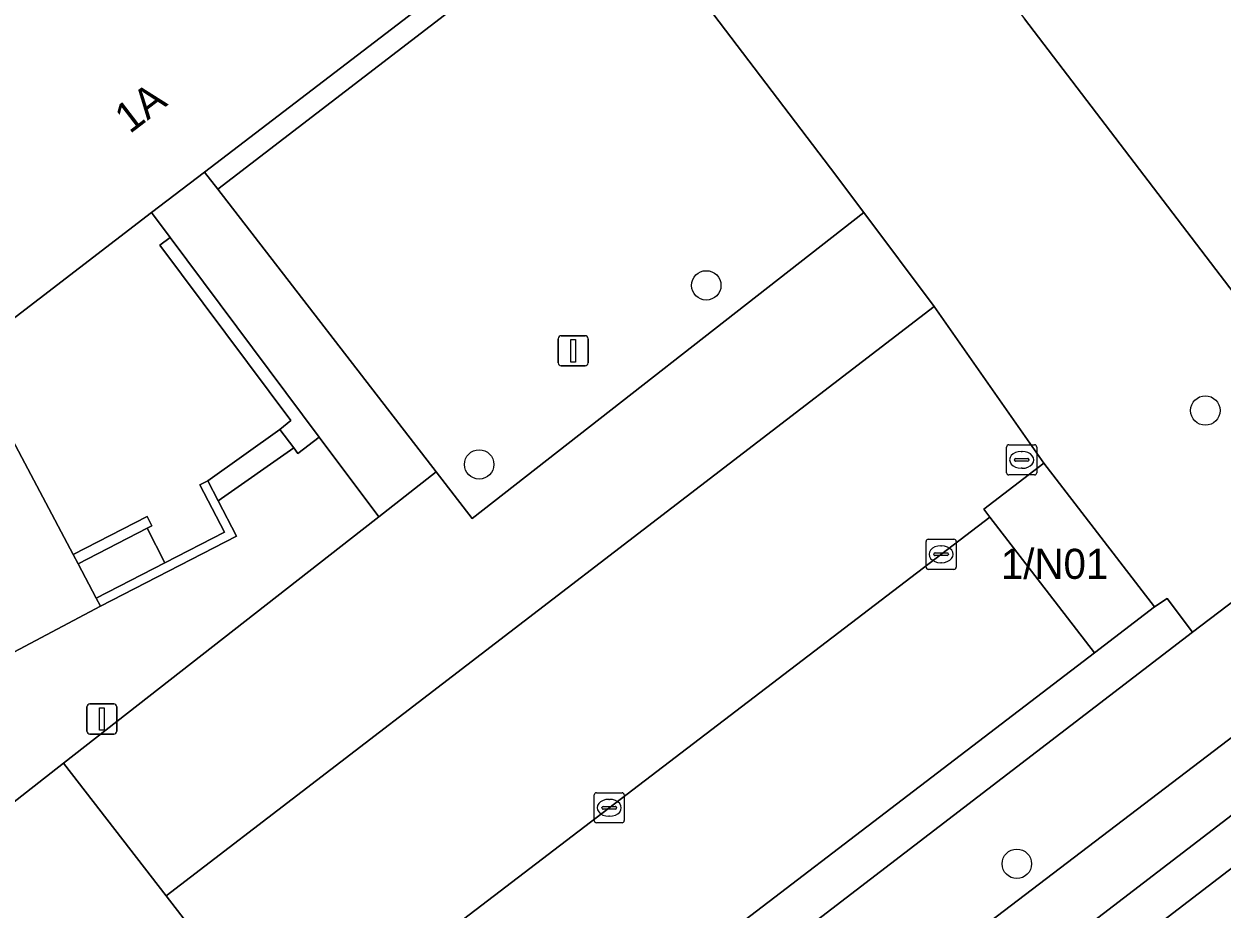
# Model space of a CAD drawing. Extents: x 159352 to 160617, y 385888 to 387323.
# Drawn here: x 159906.78 to 159946.57, y 386522.75 to 386552.16 of the extents above; entities that cross this region are included whole.
import ezdxf

# ---------------------------------------------------------------- set-up
doc = ezdxf.new("R2010")
doc.units = 0
for name, color, linetype in [('IMGEO_Boom', 7, 'Continuous'), ('IMGEO_Erf', 7, 'Continuous'), ('IMGEO_Groenvoorziening', 7, 'Continuous'), ('IMGEO_Haag', 7, 'Continuous'), ('IMGEO_Kolk', 7, 'Continuous'), ('IMGEO_Lichtmast', 7, 'Continuous'), ('IMGEO_Muur', 7, 'Continuous'), ('IMGEO_Pand', 7, 'Continuous'), ('IMGEO_Pand_nummerreeks', 7, 'Continuous'), ('IMGEO_Parkeervlak_gesloten', 7, 'Continuous'), ('IMGEO_Parkeervlak_open', 7, 'Continuous'), ('IMGEO_Rijbaan_lokaal_gesloten', 7, 'Continuous'), ('IMGEO_Rijbaan_lokaal_open', 7, 'Continuous'), ('IMGEO_Rioolput', 7, 'Continuous'), ('IMGEO_Voetpad_open', 7, 'Continuous')]:
    doc.layers.add(name, color=color, linetype=linetype)

msp = doc.modelspace()

# ---------------------------------------------------------------- linework, layer by layer
at = {"layer": 'IMGEO_Boom'}
for centre in [(159929.438, 386543.471), (159946.013, 386539.313), (159921.896, 386537.523), (159939.754, 386524.256)]:
    msp.add_circle(centre, 0.489, dxfattribs=at)
at = {"layer": 'IMGEO_Erf'}
msp.add_lwpolyline([(159918.853, 386623.383), (159898.089, 386607.292), (159922.277, 386575.578), (159940.008, 386552.331), (159951.895, 386536.745), (159972.553, 386552.445)], dxfattribs=at)
msp.add_lwpolyline([(159912.775, 386547.236), (159913.211, 386546.671), (159924.505, 386555.352), (159918.33, 386563.284), (159917.807, 386562.877), (159920.456, 386559.419), (159923.497, 386555.45)], close=True, dxfattribs=at)
at = {"layer": 'IMGEO_Groenvoorziening'}
for points in [[(159920.36, 386564.743), (159918.33, 386563.284), (159924.505, 386555.352), (159913.211, 386546.671), (159920.47, 386537.273), (159921.661, 386535.731), (159934.672, 386545.892), (159933.568, 386547.368)], [(159942.332, 386531.263), (159923.967, 386517.223), (159924.868, 386516.046), (159945.59, 386531.953), (159944.745, 386533.066), (159944.324, 386532.797)]]:
    msp.add_lwpolyline(points, close=True, dxfattribs=at)
msp.add_lwpolyline([(159920.36, 386564.743), (159933.568, 386547.368), (159934.672, 386545.892), (159937.004, 386542.774), (159940.649, 386537.568), (159944.324, 386532.797), (159944.745, 386533.066), (159945.59, 386531.953), (159951.895, 386536.745), (159940.008, 386552.331)], dxfattribs=at)
at = {"layer": 'IMGEO_Haag'}
msp.add_lwpolyline([(159942.332, 386531.263), (159923.967, 386517.223), (159924.868, 386516.046), (159945.59, 386531.953), (159944.745, 386533.066), (159944.324, 386532.797)], close=True, dxfattribs=at)
at = {"layer": 'IMGEO_Kolk'}
for p, q in [((159936.813, 386535.038), (159937.665, 386535.038)), ((159936.738, 386534.112), (159936.738, 386534.964)), ((159937.226, 386534.818), (159937.251, 386534.818)), ((159937.739, 386534.964), (159937.739, 386534.112)), ((159936.997, 386534.532), (159936.997, 386534.544)), ((159937.435, 386534.495), (159937.037, 386534.495)), ((159937.04, 386534.581), (159937.438, 386534.581)), ((159937.249, 386534.258), (159937.224, 386534.258)), ((159937.481, 386534.544), (159937.481, 386534.532)), ((159937.665, 386534.038), (159936.813, 386534.038)), ((159925.714, 386525.691), (159925.714, 386526.543)), ((159925.789, 386526.617), (159926.641, 386526.617)), ((159926.202, 386526.397), (159926.227, 386526.397)), ((159926.715, 386526.543), (159926.715, 386525.691)), ((159925.973, 386526.111), (159925.973, 386526.123)), ((159926.411, 386526.074), (159926.013, 386526.074)), ((159926.016, 386526.16), (159926.414, 386526.16)), ((159926.225, 386525.837), (159926.2, 386525.837)), ((159926.457, 386526.123), (159926.457, 386526.111)), ((159926.641, 386525.617), (159925.789, 386525.617))]:
    msp.add_line(p, q, dxfattribs=at)
for points in [[(159936.813, 386535.038), (159937.665, 386535.038)], [(159936.738, 386534.112), (159936.738, 386534.964)], [(159937.739, 386534.964), (159937.739, 386534.112)], [(159937.665, 386534.038), (159936.813, 386534.038)], [(159925.714, 386525.691), (159925.714, 386526.543)], [(159925.789, 386526.617), (159926.641, 386526.617)], [(159926.715, 386526.543), (159926.715, 386525.691)], [(159926.641, 386525.617), (159925.789, 386525.617)]]:
    msp.add_lwpolyline(points, dxfattribs=at)
for centre, radius, start, end in [((159936.815, 386534.962), 0.0765, 91.552, 178.448), ((159936.815, 386534.962), 0.0765, 91.552, 178.448), ((159937.663, 386534.962), 0.0765, 1.552, 88.448), ((159937.663, 386534.962), 0.0765, 1.552, 88.448), ((159937.037, 386534.541), 0.0403, 85.8775, 175.7526), ((159937.034, 386534.531), 0.0366, 178.938, 274.7102), ((159937.438, 386534.538), 0.043, 264.8664, 352.4533), ((159937.442, 386534.543), 0.0386, 1.7309, 96.639), ((159936.815, 386534.114), 0.0765, 181.552, 268.448), ((159936.815, 386534.114), 0.0765, 181.552, 268.448), ((159937.663, 386534.114), 0.0765, 271.552, 358.448), ((159937.663, 386534.114), 0.0765, 271.552, 358.448), ((159925.791, 386526.541), 0.0765, 91.552, 178.448), ((159925.791, 386526.541), 0.0765, 91.552, 178.448), ((159926.639, 386526.541), 0.0765, 1.552, 88.448), ((159926.639, 386526.541), 0.0765, 1.552, 88.448), ((159926.013, 386526.12), 0.0403, 85.8775, 175.7526), ((159926.01, 386526.11), 0.0366, 178.938, 274.7102), ((159926.414, 386526.117), 0.043, 264.8664, 352.4533), ((159926.418, 386526.122), 0.0386, 1.7309, 96.639), ((159925.791, 386525.693), 0.0765, 181.552, 268.448), ((159925.791, 386525.693), 0.0765, 181.552, 268.448), ((159926.639, 386525.693), 0.0765, 271.552, 358.448), ((159926.639, 386525.693), 0.0765, 271.552, 358.448)]:
    msp.add_arc(centre, radius, start, end, dxfattribs=at)
for centre, major_axis, ratio, start_param, end_param in [((159937.225, 386534.538), (-0.387, 0.002), 0.722429, 4.712389, 7.853982), ((159937.25, 386534.538), (-0.39, 0.002), 0.717154, 1.570796, 4.712389), ((159926.201, 386526.117), (-0.387, 0.002), 0.722429, 4.712389, 7.853982), ((159926.226, 386526.117), (-0.39, 0.002), 0.717154, 1.570796, 4.712389)]:
    msp.add_ellipse(centre, major_axis=major_axis, ratio=ratio, start_param=start_param, end_param=end_param, dxfattribs=at)
at = {"layer": 'IMGEO_Lichtmast'}
for p, q in [((159924.624, 386541.798), (159925.414, 386541.798)), ((159925.414, 386541.798), (159924.624, 386541.798)), ((159924.524, 386540.898), (159924.524, 386541.698)), ((159924.524, 386541.698), (159924.524, 386540.898)), ((159925.514, 386541.698), (159925.514, 386540.898)), ((159925.514, 386540.898), (159925.514, 386541.698)), ((159925.414, 386540.798), (159924.624, 386540.798)), ((159924.624, 386540.798), (159925.414, 386540.798)), ((159908.87, 386528.665), (159908.87, 386529.465)), ((159908.87, 386529.465), (159908.87, 386528.665)), ((159908.97, 386529.565), (159909.76, 386529.565)), ((159909.76, 386529.565), (159908.97, 386529.565)), ((159909.86, 386529.465), (159909.86, 386528.665)), ((159909.86, 386528.665), (159909.86, 386529.465)), ((159909.76, 386528.565), (159908.97, 386528.565)), ((159908.97, 386528.565), (159909.76, 386528.565))]:
    msp.add_line(p, q, dxfattribs=at)
for points in [[(159924.944, 386541.673), (159925.094, 386541.673), (159925.094, 386540.923), (159924.944, 386540.923), (159924.944, 386541.673)], [(159909.29, 386529.44), (159909.44, 386529.44), (159909.44, 386528.69), (159909.29, 386528.69), (159909.29, 386529.44)]]:
    msp.add_lwpolyline(points, dxfattribs=at)
for centre, start, end in [((159924.624, 386541.698), 90, 180), ((159924.624, 386541.698), 90, 180), ((159925.414, 386541.698), 0, 90), ((159925.414, 386541.698), 360, 90), ((159924.624, 386540.898), 180, 270), ((159924.624, 386540.898), 180, 270), ((159925.414, 386540.898), 270, 0), ((159925.414, 386540.898), 270, 0), ((159908.97, 386529.465), 90, 180), ((159908.97, 386529.465), 90, 180), ((159909.76, 386529.465), 0, 90), ((159909.76, 386529.465), 360, 90), ((159908.97, 386528.665), 180, 270), ((159908.97, 386528.665), 180, 270), ((159909.76, 386528.665), 270, 0), ((159909.76, 386528.665), 270, 0)]:
    msp.add_arc(centre, 0.1, start, end, dxfattribs=at)
at = {"layer": 'IMGEO_Muur'}
for points in [[(159915.87, 386537.889), (159916.586, 386538.424), (159911.633, 386545.058), (159911.292, 386544.804), (159915.64, 386538.98), (159915.277, 386538.684), (159915.736, 386538.069)], [(159909.321, 386532.811), (159913.837, 386535.135), (159913.229, 386536.316), (159912.886, 386536.982), (159912.622, 386536.846), (159913.433, 386535.272), (159911.459, 386534.256), (159909.178, 386533.081)], [(159908.573, 386534.224), (159910.866, 386535.406), (159911.024, 386535.487), (159910.864, 386535.798), (159908.409, 386534.534)]]:
    msp.add_lwpolyline(points, close=True, dxfattribs=at)
at = {"layer": 'IMGEO_Pand'}
for points in [[(159912.832, 386568.343), (159903.749, 386561.385), (159888.901, 386550.01), (159891.905, 386544.265), (159894.222, 386539.834), (159895.04, 386540.46), (159898.46, 386535.994), (159897.087, 386534.942), (159897.179, 386534.822), (159901.779, 386528.816), (159909.321, 386532.811), (159909.178, 386533.081), (159908.573, 386534.224), (159908.409, 386534.534), (159904.884, 386541.191), (159911.014, 386545.887), (159912.775, 386547.236), (159923.497, 386555.45), (159920.456, 386559.419), (159917.807, 386562.877), (159913.328, 386568.723)], [(159944.324, 386532.797), (159940.649, 386537.568), (159938.657, 386536.034), (159938.858, 386535.773), (159942.332, 386531.263)]]:
    msp.add_lwpolyline(points, close=True, dxfattribs=at)
at = {"layer": 'IMGEO_Parkeervlak_gesloten'}
for points in [[(159876.924, 386472.328), (159899.739, 386489.718), (159978.286, 386549.954), (159978.068, 386550.238), (159977.564, 386550.208), (159975.608, 386550.229)], [(159974.688, 386549.863), (159970.339, 386546.5), (159949.802, 386530.673), (159926.982, 386513.283), (159924.258, 386511.207), (159921.752, 386509.284), (159911.446, 386501.377), (159909.661, 386500), (159905.719, 386496.959), (159899.555, 386492.261), (159893.309, 386487.448), (159887.281, 386482.827), (159886.65, 386482.339), (159878.181, 386475.807)]]:
    msp.add_lwpolyline(points, dxfattribs=at)
at = {"layer": 'IMGEO_Parkeervlak_open'}
for points in [[(159937.004, 386542.774), (159934.672, 386545.892), (159921.661, 386535.731), (159920.47, 386537.273), (159918.56, 386535.78), (159918.014, 386535.354), (159908.093, 386527.599), (159911.495, 386523.195), (159921.481, 386530.86)], [(159938.858, 386535.773), (159919.966, 386521.341), (159923.468, 386516.842), (159923.967, 386517.223), (159942.332, 386531.263)], [(159911.495, 386523.195), (159908.093, 386527.599), (159903.673, 386524.147), (159904.781, 386522.645), (159904.919, 386522.517), (159905.493, 386521.701), (159906.02, 386521.077), (159914.482, 386510.005), (159918.729, 386513.236), (159919.018, 386513.456)]]:
    msp.add_lwpolyline(points, close=True, dxfattribs=at)
at = {"layer": 'IMGEO_Rijbaan_lokaal_gesloten'}
for points in [[(159859.708, 386457.258), (159979.14, 386548.844), (159978.286, 386549.954), (159899.739, 386489.718), (159876.924, 386472.328), (159870.066, 386467.048), (159858.807, 386458.451)], [(159862.162, 386454.007), (159981.625, 386545.617), (159979.14, 386548.844), (159859.708, 386457.258)]]:
    msp.add_lwpolyline(points, close=True, dxfattribs=at)
at = {"layer": 'IMGEO_Rijbaan_lokaal_open'}
msp.add_lwpolyline([(159938.858, 386535.773), (159938.657, 386536.034), (159940.649, 386537.568), (159937.004, 386542.774), (159921.481, 386530.86), (159911.495, 386523.195), (159919.018, 386513.456), (159923.468, 386516.842), (159919.966, 386521.341)], close=True, dxfattribs=at)
at = {"layer": 'IMGEO_Rioolput'}
for p, q in [((159939.489, 386538.175), (159940.341, 386538.175)), ((159939.414, 386537.249), (159939.414, 386538.101)), ((159939.902, 386537.955), (159939.927, 386537.955)), ((159940.415, 386538.101), (159940.415, 386537.249)), ((159939.673, 386537.669), (159939.673, 386537.681)), ((159940.111, 386537.632), (159939.713, 386537.632)), ((159939.716, 386537.718), (159940.114, 386537.718)), ((159939.925, 386537.395), (159939.9, 386537.395)), ((159940.157, 386537.681), (159940.157, 386537.669)), ((159940.341, 386537.175), (159939.489, 386537.175))]:
    msp.add_line(p, q, dxfattribs=at)
for points in [[(159939.489, 386538.175), (159940.341, 386538.175)], [(159939.414, 386537.249), (159939.414, 386538.101)], [(159940.415, 386538.101), (159940.415, 386537.249)], [(159940.341, 386537.175), (159939.489, 386537.175)]]:
    msp.add_lwpolyline(points, dxfattribs=at)
for centre, radius, start, end in [((159939.491, 386538.099), 0.0765, 91.552, 178.448), ((159939.491, 386538.099), 0.0765, 91.552, 178.448), ((159940.339, 386538.099), 0.0765, 1.552, 88.448), ((159940.339, 386538.099), 0.0765, 1.552, 88.448), ((159939.713, 386537.678), 0.0403, 85.8775, 175.7526), ((159939.71, 386537.668), 0.0366, 178.938, 274.7102), ((159940.114, 386537.675), 0.043, 264.8664, 352.4533), ((159940.118, 386537.68), 0.0386, 1.7309, 96.639), ((159939.491, 386537.251), 0.0765, 181.552, 268.448), ((159939.491, 386537.251), 0.0765, 181.552, 268.448), ((159940.339, 386537.251), 0.0765, 271.552, 358.448), ((159940.339, 386537.251), 0.0765, 271.552, 358.448)]:
    msp.add_arc(centre, radius, start, end, dxfattribs=at)
for centre, major_axis, ratio, start_param, end_param in [((159939.901, 386537.675), (-0.387, 0.002), 0.722429, 4.712389, 7.853982), ((159939.926, 386537.675), (-0.39, 0.002), 0.717154, 1.570796, 4.712389)]:
    msp.add_ellipse(centre, major_axis=major_axis, ratio=ratio, start_param=start_param, end_param=end_param, dxfattribs=at)
at = {"layer": 'IMGEO_Voetpad_open'}
msp.add_lwpolyline([(159981.696, 386559.33), (159972.591, 386552.445), (159972.553, 386552.445), (159951.895, 386536.745), (159945.59, 386531.953), (159924.868, 386516.046), (159926.982, 386513.283), (159949.802, 386530.673), (159970.339, 386546.5), (159974.688, 386549.863)], dxfattribs=at)
for points in [[(159920.47, 386537.273), (159913.211, 386546.671), (159912.775, 386547.236), (159911.014, 386545.887), (159911.633, 386545.058), (159916.586, 386538.424), (159918.56, 386535.78)], [(159908.409, 386534.534), (159910.864, 386535.798), (159911.024, 386535.487), (159910.866, 386535.406), (159911.459, 386534.256), (159913.433, 386535.272), (159912.622, 386536.846), (159912.886, 386536.982), (159915.277, 386538.684), (159915.64, 386538.98), (159911.292, 386544.804), (159911.633, 386545.058), (159911.014, 386545.887), (159904.884, 386541.191)], [(159913.229, 386536.316), (159915.736, 386538.069), (159915.277, 386538.684), (159912.886, 386536.982)], [(159918.014, 386535.354), (159918.56, 386535.78), (159916.586, 386538.424), (159915.87, 386537.889), (159915.736, 386538.069), (159913.229, 386536.316), (159913.837, 386535.135), (159909.321, 386532.811), (159901.779, 386528.816), (159897.179, 386534.822), (159896.116, 386534.035), (159903.673, 386524.147), (159908.093, 386527.599)], [(159909.178, 386533.081), (159911.459, 386534.256), (159910.866, 386535.406), (159908.573, 386534.224)]]:
    msp.add_lwpolyline(points, close=True, dxfattribs=at)

# ---------------------------------------------------------------- texts
at = {"layer": 'IMGEO_Pand_nummerreeks'}
msp.add_text('1A', height=1, rotation=37.4549, dxfattribs=at).set_placement((159910.289, 386548.487))
msp.add_text('1/N01', height=1, dxfattribs=at).set_placement((159939.222, 386533.721))

doc.saveas('drawing.dxf')
